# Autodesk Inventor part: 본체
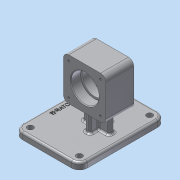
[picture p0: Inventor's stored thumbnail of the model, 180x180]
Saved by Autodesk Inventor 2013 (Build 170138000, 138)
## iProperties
Created: 2020-11
Part Number: 본체
Material: 알루미늄 6061
Document SubType Name: Modeling
Designer: Administrator
Density: 2.71 g/cm^3
Mass: 685.609 g
Surface Area: 543.155 cm^2
Volume: 252.992 cm^3
Author: Administrator
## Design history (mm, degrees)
sketch "스케치1"
  geometry: L1 (-65, 49)-(65, 49); L2 (65, 49)-(65, -49); L3 (65, -49)-(-65, -49); L4 (-65, -49)-(-65, 49); L5 (-65, 49)-(65, -49); L6 (65, 49)-(-65, -49); 1 further point
  constraints: 12 end point, 2 midpoint, 2 parallel, 1 horizontal, 1 perpendicular
  dimensions: "d0" = 130 distance of L1.start L1.end; "d2" = 98 distance of L1.end L2.end
extrude "돌출1" new body sketch "스케치1" distance "d3" = 10; taper "d4" = 0 deg
sketch "스케치3"
  geometry: L1 (-19, 102)-(45, 102); L2 (45, 102)-(45, 38); L3 (45, 38)-(-19, 38); L4 (-19, 38)-(-19, 102); L5 (-19, 102)-(45, 38); L6 (45, 102)-(-19, 38); L7 (-49, 0)-(49, 0) reference; L8 (-49, 0)-(-49, 10) reference; 2 further points
  constraints: 12 end point, 2 midpoint, 2 parallel, 2 perpendicular, 1 horizontal
  dimensions: "d12" = 64 distance of L2.end L3.end; "d14" = 70 distance from line of L7 point (13, 70); "d15" = 62 distance from line of point (13, 70) L8
extrude "돌출3" join sketch "스케치3" stored distance "d16" = 42; taper "d17" = 0 deg
sketch "스케치4"
  geometry: L1 (-38, -19)-(-38, 45) reference; L2 (0, 49)-(0, -49) reference; C1 r 18 at (-70, 13); 2 further points
  constraints: 1 centre point, 1 horizontal alignment, 1 midpoint
  dimensions: "d18" = 70 distance from line of L2 C1.centre; "d19" = 36 diameter of C1
extrude "돌출4" cut sketch "스케치4" distance "d20" = 42; taper "d21" = 0 deg
hole "구멍1" diameter "d24" = 42; stored, may be unused: countersink angle "d28" = 90 deg, drill point angle "d30" = 0 deg; dims "d25" = 6, "d26" = 4, "d27" = 2, "d29" = 15, "d56" = 10, "d57" = 10
fillet "모깎기1" dims "d31" = 8
sketch "스케치5"
  geometry: L1 (37, 38)-(-11, 38) reference; L2 (49, 10)-(-49, 10) reference; L3 (-7, 40.585)-(33, 40.585); L4 (33, 40.585)-(33, 5.169); L5 (33, 5.169)-(-7, 5.169); L6 (-7, 5.169)-(-7, 40.585); L7 (-49, 0)-(49, 0) reference; 3 further points
  constraints: 8 end point, 2 midpoint, 2 parallel, 1 horizontal, 1 perpendicular, 1 vertical alignment
  dimensions: "d32" = 40 distance of L4.end L5.end; "d34" = 5.16861 distance between parallel lines of L7 L5; "d35" = 35.41667 distance of L5.end L3.start
extrude "돌출5" join sketch "스케치5" stored distance "d36" = 8; taper "d37" = 0 deg
node "작업 평면4"
  node "작업 평면3"
sketch "스케치6"
  geometry: L1 (-86, -38)-(-44, -38) reference; L2 (-48, -45.334)-(-82, -45.334); L3 (-82, -45.334)-(-82, -5.334); L4 (-82, -5.334)-(-48, -5.334); L5 (-48, -5.334)-(-48, -45.334); L6 (0, 0)-(-130, 0) reference; 3 further points
  constraints: 8 end point, 2 midpoint, 2 parallel, 1 horizontal, 1 perpendicular, 1 vertical alignment
  dimensions: "d39" = 34 distance of L3.end L4.end; "d41" = 5.33397 distance between parallel lines of L6 L4; "d42" = 40 distance of L4.end L2.start
extrude "돌출6" join sketch "스케치6" stored distance "d43" = 8; taper "d44" = 0 deg
chamfer "모따기1" distance "d45" = 1; stored, may be unused: second distance "d46" = 2, angle "d47" = 45 deg
fillet "모깎기2" dims "d48" = 0.3
sketch "스케치7"
  geometry: A1 r 8 centre (-94, -11) between (-102, -11) and (-94, -19) reference; 2 further points
  constraints: 1 coincident
hole "구멍2" sketch "스케치7" at (-94, -11) diameter "d49" = 3.242; stored, may be unused: countersink angle "d53" = 90 deg, drill point angle "d55" = 118 deg; dims "d50" = 8, "d51" = 4, "d52" = 2, "d54" = 10
fillet "모깎기3" dims "d64" = 3
fillet "모깎기4" dims "d65" = 3
fillet "모깎기5" dims "d66" = 12
fillet "모깎기6" dims "d67" = 3
hole "구멍3" diameter "d70" = 9; stored, may be unused: countersink angle "d74" = 90 deg, drill point angle "d76" = 0 deg; dims "d68" = 10, "d69" = 10, "d71" = 8, "d72" = 4, "d73" = 2, "d75" = 10
hole "구멍4" diameter "d79" = 9; stored, may be unused: countersink angle "d83" = 90 deg, drill point angle "d85" = 0 deg; dims "d77" = 10, "d78" = 10, "d80" = 8, "d81" = 4, "d82" = 2, "d84" = 10
hole "구멍5" diameter "d88" = 9; stored, may be unused: countersink angle "d92" = 90 deg, drill point angle "d94" = 0 deg; dims "d86" = 10, "d87" = 10, "d89" = 8, "d90" = 4, "d91" = 2, "d93" = 10
hole "구멍6" diameter "d97" = 9; stored, may be unused: countersink angle "d101" = 90 deg, drill point angle "d103" = 0 deg; dims "d95" = 10, "d96" = 10, "d98" = 8, "d99" = 4, "d100" = 2, "d102" = 10
sketch "스케치8"
  geometry: L1 (-53, -49)-(53, -49) reference; L2 (-65, 37)-(-65, -37) reference; 5 further points
  constraints: 1 other
  dimensions: "d106" = 10 distance from line of L1 point (0, -39); "d107" = 65 distance from line of L2 point (0, -39)
feature "엠보싱1" sketch "스케치8" dims "d0" = 130, "d2" = 98, "d108" = 0.5, "d109" = 0
node "솔리드1"
mirror "대칭1"
pattern_linear "직사각형 패턴1" dims "d60" = 48, "d63" = 48
mirror "대칭2"
other parameters: "d38" = -36
